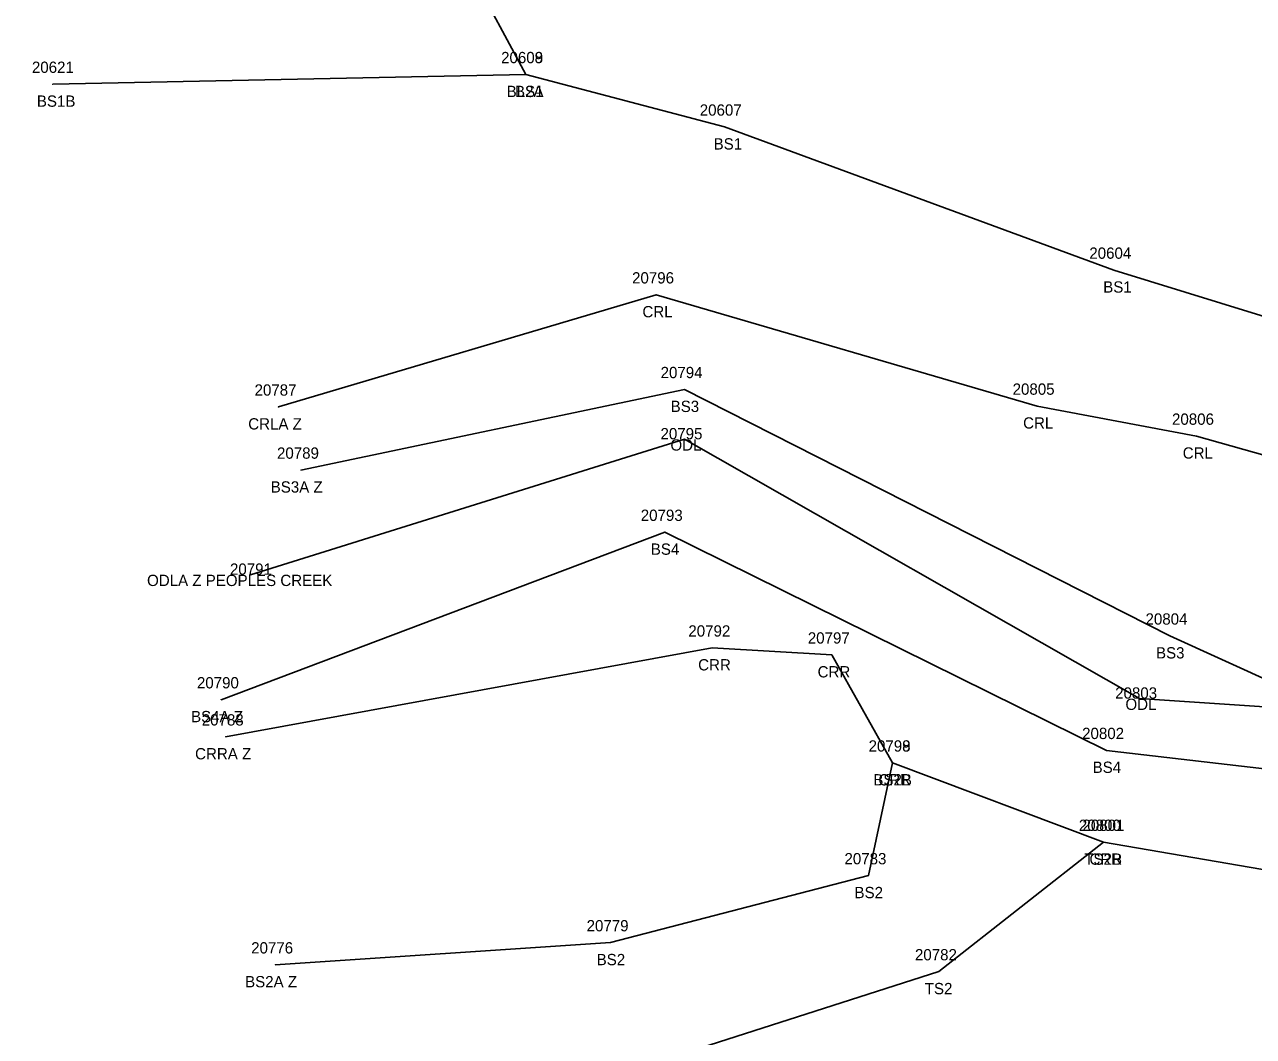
# Model space of a CAD drawing. Extents: x 1813127 to 1814107, y 1178171 to 1179078.
# Drawn here: x 1813477.1 to 1813586.1, y 1178650.6 to 1178740.3 of the extents above; entities that cross this region are included whole.
import ezdxf

# ---------------------------------------------------------------- set-up
doc = ezdxf.new("R2010")
doc.units = 0
for name, color, linetype in [('RD_DTM_BkLn1', 7, 'Continuous'), ('RD_DTM_BkLn2', 7, 'Continuous'), ('RD_EX_H2O', 7, 'Continuous'), ('RD_EX_H2O_txCode', 7, 'Continuous'), ('RD_SMD_Locator', 7, 'Continuous'), ('RD_SMD_Misc', 7, 'Continuous')]:
    doc.layers.add(name, color=color, linetype=linetype)

msp = doc.modelspace()

# ---------------------------------------------------------------- linework, layer by layer
at = {"layer": 'RD_DTM_BkLn1'}
msp.add_lwpolyline([(1813521.54, 1178735.83), (1813516.61, 1178745.01), (1813509.8, 1178754.82), (1813493.76, 1178758.2), (1813445.29, 1178767.72), (1813423.54, 1178771.64)], dxfattribs=at)
at = {"layer": 'RD_DTM_BkLn2'}
for points in [[(1813501.61, 1178700.78), (1813535.62, 1178707.92), (1813578.65, 1178686.08), (1813588.2, 1178681.74), (1813622.61, 1178682.2), (1813653.79, 1178685.74), (1813685.17, 1178685.29), (1813723.1, 1178689.85), (1813736.83, 1178692.71), (1813771.26, 1178719.75), (1813784.46, 1178726.39), (1813801.14, 1178736.57), (1813819.08, 1178738.18), (1813840.25, 1178734.78), (1813848.44, 1178735.38), (1813862.15, 1178734.12), (1813885.61, 1178732.56), (1813903.34, 1178733.15)], [(1813719.9, 1178693.61), (1813672.18, 1178710.76), (1813660.65, 1178725.82), (1813637.51, 1178719.78), (1813596.2, 1178711.55), (1813573.69, 1178718.5), (1813539.15, 1178731.18), (1813521.54, 1178735.83), (1813479.61, 1178734.97)], [(1813494.55, 1178680.43), (1813533.86, 1178695.27), (1813573.03, 1178675.94), (1813630.33, 1178669.28), (1813656.92, 1178672.11), (1813691.39, 1178675.03), (1813721.31, 1178671.27), (1813738.7, 1178671.81), (1813780.2, 1178710.54), (1813805.93, 1178727.26), (1813819.91, 1178727.35), (1813841.4, 1178723.71), (1813860.66, 1178719.9), (1813869.89, 1178724.9), (1813872.35, 1178725.71), (1813884.47, 1178724.42), (1813903.61, 1178724.04)], [(1813499.34, 1178656.94), (1813529.06, 1178658.9), (1813551.92, 1178664.84), (1813554.06, 1178674.83)], [(1813499.93, 1178646.84), (1813530.8, 1178647.58), (1813558.17, 1178656.33), (1813572.78, 1178667.8)]]:
    msp.add_lwpolyline(points, dxfattribs=at)
at = {"layer": 'RD_EX_H2O'}
for points in [[(1813497.15, 1178691.5), (1813535.61, 1178703.5), (1813575.96, 1178680.52), (1813619.86, 1178677.62), (1813650.02, 1178676.71), (1813688.26, 1178680.15), (1813722.87, 1178676.67), (1813738.45, 1178684.24), (1813776.33, 1178715.9), (1813785.2, 1178724.07), (1813802.21, 1178734.6), (1813820.03, 1178732.78), (1813837.63, 1178729.78), (1813857.38, 1178730.32)], [(1813499.62, 1178706.37), (1813533.11, 1178716.31), (1813566.87, 1178706.45), (1813581.02, 1178703.79), (1813602.73, 1178697.66), (1813630.18, 1178688.94), (1813658.74, 1178690.22), (1813683.52, 1178690.56), (1813719.9, 1178693.61)], [(1813494.93, 1178677.14), (1813538.08, 1178685.02), (1813548.67, 1178684.4), (1813554.06, 1178674.83), (1813572.78, 1178667.8), (1813599.8, 1178663.18), (1813623.26, 1178662.12), (1813655.35, 1178662.6), (1813687.65, 1178668.53), (1813720.68, 1178667.78), (1813740.16, 1178669.89)]]:
    msp.add_lwpolyline(points, dxfattribs=at)
at = {"layer": 'RD_SMD_Locator'}
for centre in [(1813521.54, 1178735.83), (1813521.54, 1178735.83), (1813479.61, 1178734.97), (1813539.15, 1178731.18), (1813573.69, 1178718.5), (1813533.11, 1178716.31), (1813535.62, 1178707.92), (1813566.87, 1178706.45), (1813499.62, 1178706.37), (1813535.61, 1178703.5), (1813581.02, 1178703.79), (1813501.61, 1178700.78), (1813533.86, 1178695.27), (1813497.15, 1178691.5), (1813578.65, 1178686.08), (1813538.08, 1178685.02), (1813548.67, 1178684.4), (1813494.55, 1178680.43), (1813575.96, 1178680.52), (1813494.93, 1178677.14), (1813573.03, 1178675.94), (1813554.06, 1178674.83), (1813554.06, 1178674.83), (1813572.78, 1178667.8), (1813572.78, 1178667.8), (1813551.92, 1178664.84), (1813529.06, 1178658.9), (1813499.34, 1178656.94), (1813558.17, 1178656.33)]:
    msp.add_circle(centre, 0.001, dxfattribs=at)

# ---------------------------------------------------------------- texts
at = {"layer": 'RD_EX_H2O_txCode'}
for s, p in [('20796', (1813530.97, 1178717.31)), ('CRL', (1813531.89, 1178714.31)), ('20787', (1813497.5, 1178707.37)), ('20805', (1813564.71, 1178707.45)), ('CRLA Z', (1813496.94, 1178704.37)), ('CRL', (1813565.64, 1178704.45)), ('20806', (1813578.84, 1178704.79)), ('20795', (1813533.49, 1178703.5)), ('ODL', (1813534.37, 1178702.5)), ('CRL', (1813579.79, 1178701.79)), ('20791', (1813495.32, 1178691.5)), ('ODLA Z PEOPLES CREEK', (1813487.97, 1178690.5)), ('20792', (1813535.96, 1178686.02)), ('20797', (1813546.55, 1178685.4)), ('CRR', (1813536.83, 1178683.02)), ('CRR', (1813547.42, 1178682.4)), ('20803', (1813573.8, 1178680.52)), ('ODL', (1813574.71, 1178679.52)), ('20788', (1813492.82, 1178678.14)), ('CRRA Z', (1813492.23, 1178675.14)), ('20798', (1813551.94, 1178675.83)), ('CRR', (1813552.81, 1178672.83)), ('20800', (1813570.58, 1178668.8)), ('CRR', (1813571.52, 1178665.8))]:
    msp.add_text(s, height=1, dxfattribs=at).set_placement(p)
at = {"layer": 'RD_SMD_Misc'}
for s, p in [('20621', (1813477.76, 1178735.97)), ('20608', (1813519.36, 1178736.83)), ('20609', (1813519.36, 1178736.83)), ('BL2A', (1813519.85, 1178733.83)), ('BS1', (1813520.59, 1178733.83)), ('BS1B', (1813478.2, 1178732.97)), ('20607', (1813536.97, 1178732.18)), ('BS1', (1813538.2, 1178729.18)), ('20604', (1813571.51, 1178719.5)), ('BS1', (1813572.74, 1178716.5)), ('20794', (1813533.5, 1178708.92)), ('BS3', (1813534.39, 1178705.92)), ('20789', (1813499.49, 1178701.78)), ('BS3A Z', (1813498.93, 1178698.78)), ('20793', (1813531.74, 1178696.27)), ('BS4', (1813532.63, 1178693.27)), ('20804', (1813576.49, 1178687.08)), ('BS3', (1813577.42, 1178684.08)), ('20790', (1813492.39, 1178681.43)), ('BS4A Z', (1813491.87, 1178678.43)), ('20802', (1813570.87, 1178676.94)), ('20799', (1813551.94, 1178675.83)), ('BS4', (1813571.8, 1178673.94)), ('BS2B', (1813552.36, 1178672.83)), ('20801', (1813570.9, 1178668.8)), ('20783', (1813549.8, 1178665.84)), ('TS2B', (1813571.06, 1178665.8)), ('BS2', (1813550.69, 1178662.84)), ('20779', (1813526.94, 1178659.9)), ('20776', (1813497.2, 1178657.94)), ('BS2', (1813527.83, 1178656.9)), ('20782', (1813556.05, 1178657.33)), ('BS2A Z', (1813496.66, 1178654.94)), ('TS2', (1813556.92, 1178654.33))]:
    msp.add_text(s, height=1, dxfattribs=at).set_placement(p)

doc.saveas('drawing.dxf')
